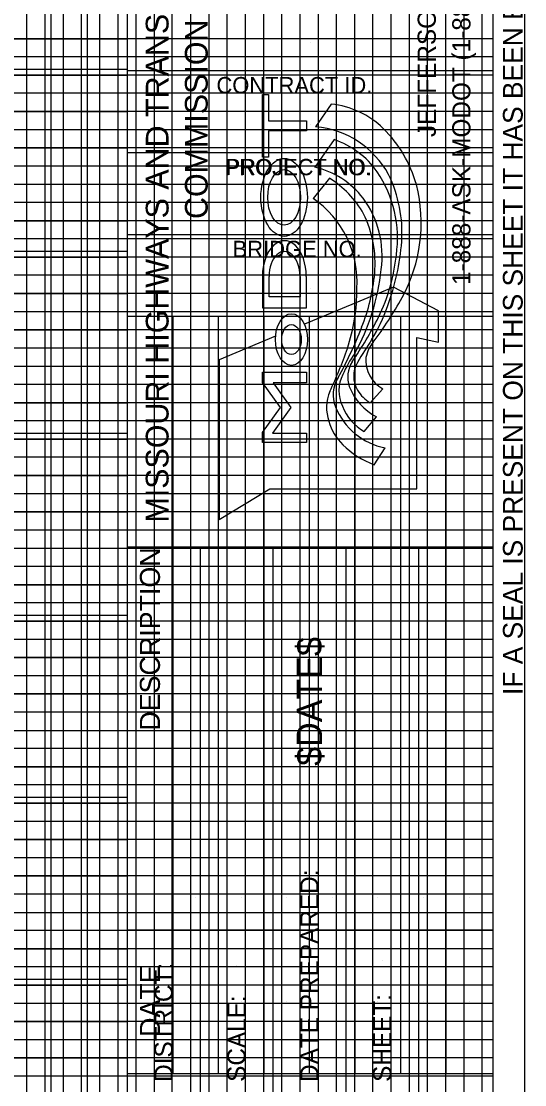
# Model space of a CAD drawing. Extents: x 0 to 31.6, y 0 to 20.8.
# Drawn here: x 28.84 to 31.6, y 10.27 to 16.11 of the extents above; entities that cross this region are included whole.
import ezdxf

# ---------------------------------------------------------------- set-up
doc = ezdxf.new("R2010")
doc.units = 0
for name, color, linetype in [('Border-Border', 7, 'Continuous'), ('Border-Bridge xsection major grid lines', 7, 'Continuous'), ('Border-Bridge xsection minor grid lines', 7, 'Continuous'), ('Border-Full profile major grid lines', 7, 'Continuous'), ('Border-Full xsection major grid lines', 7, 'Continuous'), ('Border-Full xsection minor grid lines', 7, 'Continuous'), ('Border-Plotting block', 7, 'Continuous'), ('Border-Title block - Final Plans Consultant Manual Seal', 7, 'Continuous'), ('Border-Title block - Final Plans Electronic Seal', 7, 'Continuous'), ('Border-Title block - Location Survey Electronic Seal', 7, 'Continuous'), ('Border-Xsection shape', 7, 'Continuous')]:
    doc.layers.add(name, color=color, linetype=linetype)

msp = doc.modelspace()

# ---------------------------------------------------------------- linework, layer by layer
at = {"layer": 'Border-Border'}
msp.add_line((31.425, 20.5875), (31.425, 0.2125), dxfattribs=at)
at = {"layer": 'Border-Bridge xsection major grid lines'}
for p, q in [((29.6649, 4.2046), (29.6649, 20.5875)), ((30.6649, 20.5875), (30.6649, 4.2046)), ((0.175, 15.2126), (31.4249, 15.2126)), ((0.175, 14.2126), (31.4249, 14.2126)), ((0.175, 13.2125), (31.4249, 13.2125)), ((0.175, 12.2125), (31.4249, 12.2125)), ((0.175, 11.2125), (31.4249, 11.2125))]:
    msp.add_line(p, q, dxfattribs=at)
at = {"layer": 'Border-Bridge xsection minor grid lines'}
for p, q in [((28.8649, 20.5875), (28.8649, 4.2046)), ((28.9649, 20.5875), (28.9649, 4.2046)), ((29.0649, 20.5875), (29.0649, 4.2046)), ((29.1649, 20.5875), (29.1649, 4.2046)), ((29.2649, 20.5875), (29.2649, 4.2046)), ((29.3649, 20.5875), (29.3649, 4.2046)), ((29.4649, 20.5875), (29.4649, 4.2046)), ((29.5649, 20.5875), (29.5649, 4.2046)), ((29.7649, 20.5875), (29.7649, 4.2046)), ((29.8649, 20.5875), (29.8649, 4.2046)), ((29.9649, 20.5875), (29.9649, 4.2046)), ((30.0649, 20.5875), (30.0649, 4.2046)), ((30.1649, 20.5875), (30.1649, 4.2046)), ((30.2649, 20.5875), (30.2649, 4.2046)), ((30.3649, 20.5875), (30.3649, 4.2046)), ((30.4649, 20.5875), (30.4649, 4.2046)), ((30.5649, 20.5875), (30.5649, 4.2046)), ((30.7649, 20.5875), (30.7649, 4.2046)), ((30.8649, 20.5875), (30.8649, 4.2046)), ((30.9649, 20.5875), (30.9649, 4.2046)), ((31.0649, 20.5875), (31.0649, 4.2046)), ((31.1649, 20.5875), (31.1649, 4.2046)), ((31.2649, 20.5875), (31.2649, 4.2046)), ((31.3649, 20.5875), (31.3649, 4.2046)), ((31.4249, 16.0126), (0.175, 16.0126)), ((31.4249, 15.9126), (0.175, 15.9126)), ((31.4249, 15.8126), (0.175, 15.8126)), ((31.4249, 15.7126), (0.175, 15.7126)), ((31.4249, 15.6126), (0.175, 15.6126)), ((31.4249, 15.5126), (0.175, 15.5126)), ((31.4249, 15.4126), (0.175, 15.4126)), ((31.4249, 15.3126), (0.175, 15.3126)), ((31.4249, 15.1126), (0.175, 15.1126)), ((31.4249, 15.0126), (0.175, 15.0126)), ((31.4249, 14.9126), (0.175, 14.9126)), ((31.4249, 14.8126), (0.175, 14.8126)), ((31.4249, 14.7126), (0.175, 14.7126)), ((31.4249, 14.6126), (0.175, 14.6126)), ((31.4249, 14.5126), (0.175, 14.5126)), ((31.4249, 14.4126), (0.175, 14.4126)), ((31.4249, 14.3126), (0.175, 14.3126)), ((31.4249, 14.1126), (0.175, 14.1126)), ((31.4249, 14.0125), (0.175, 14.0125)), ((31.4249, 13.9125), (0.175, 13.9125)), ((31.4249, 13.8125), (0.175, 13.8125)), ((31.4249, 13.7125), (0.175, 13.7125)), ((31.4249, 13.6125), (0.175, 13.6125)), ((31.4249, 13.5125), (0.175, 13.5125)), ((31.4249, 13.4125), (0.175, 13.4125)), ((31.4249, 13.3125), (0.175, 13.3125)), ((31.4249, 13.1125), (0.175, 13.1125)), ((31.4249, 13.0125), (0.175, 13.0125)), ((31.4249, 12.9125), (0.175, 12.9125)), ((31.4249, 12.8125), (0.175, 12.8125)), ((31.4249, 12.7125), (0.175, 12.7125)), ((31.4249, 12.6125), (0.175, 12.6125)), ((31.4249, 12.5125), (0.175, 12.5125)), ((31.4249, 12.4125), (0.175, 12.4125)), ((31.4249, 12.3125), (0.175, 12.3125)), ((31.4249, 12.1125), (0.175, 12.1125)), ((31.4249, 12.0125), (0.175, 12.0125)), ((31.4249, 11.9125), (0.175, 11.9125)), ((31.4249, 11.8125), (0.175, 11.8125)), ((31.4249, 11.7125), (0.175, 11.7125)), ((31.4249, 11.6125), (0.175, 11.6125)), ((31.4249, 11.5125), (0.175, 11.5125)), ((31.4249, 11.4125), (0.175, 11.4125)), ((31.4249, 11.3125), (0.175, 11.3125)), ((31.4249, 11.1125), (0.175, 11.1125)), ((31.4249, 11.0125), (0.175, 11.0125)), ((31.4249, 10.9125), (0.175, 10.9125)), ((31.4249, 10.8125), (0.175, 10.8125)), ((31.4249, 10.7125), (0.175, 10.7125)), ((31.4249, 10.6125), (0.175, 10.6125)), ((31.4249, 10.5125), (0.175, 10.5125)), ((31.4249, 10.4125), (0.175, 10.4125)), ((31.4249, 10.3125), (0.175, 10.3125))]:
    msp.add_line(p, q, dxfattribs=at)
at = {"layer": 'Border-Full profile major grid lines'}
for p, q in [((29.4171, 15.8436), (0.175, 15.8436)), ((29.4171, 14.8436), (0.175, 14.8436)), ((29.4171, 13.8436), (0.175, 13.8436)), ((29.4171, 12.8436), (0.175, 12.8436)), ((29.4171, 11.8436), (0.175, 11.8436)), ((29.4171, 10.8436), (0.175, 10.8436))]:
    msp.add_line(p, q, dxfattribs=at)
at = {"layer": 'Border-Full xsection major grid lines'}
for p, q in [((0.175, 15.2125), (29.4171, 15.2125)), ((0.175, 14.2125), (29.4171, 14.2125)), ((0.175, 13.2125), (29.4171, 13.2125)), ((0.175, 12.2125), (29.4171, 12.2125)), ((0.175, 11.2125), (29.4171, 11.2125))]:
    msp.add_line(p, q, dxfattribs=at)
at = {"layer": 'Border-Full xsection minor grid lines'}
for p, q in [((28.9999, 0.2125), (28.9999, 20.5875)), ((29.1999, 0.2125), (29.1999, 20.5875)), ((0.175, 16.0125), (29.4171, 16.0125)), ((0.175, 15.8125), (29.4171, 15.8125)), ((0.175, 15.6125), (29.4171, 15.6125)), ((0.175, 15.4125), (29.4171, 15.4125)), ((0.175, 15.0125), (29.4171, 15.0125)), ((0.175, 14.8125), (29.4171, 14.8125)), ((0.175, 14.6125), (29.4171, 14.6125)), ((0.175, 14.4125), (29.4171, 14.4125)), ((0.175, 14.0125), (29.4171, 14.0125)), ((0.175, 13.8125), (29.4171, 13.8125)), ((0.175, 13.6125), (29.4171, 13.6125)), ((0.175, 13.4125), (29.4171, 13.4125)), ((0.175, 13.0125), (29.4171, 13.0125)), ((0.175, 12.8125), (29.4171, 12.8125)), ((0.175, 12.6125), (29.4171, 12.6125)), ((0.175, 12.4125), (29.4171, 12.4125)), ((0.175, 12.0125), (29.4171, 12.0125)), ((0.175, 11.8125), (29.4171, 11.8125)), ((0.175, 11.6125), (29.4171, 11.6125)), ((0.175, 11.4125), (29.4171, 11.4125)), ((0.175, 11.0125), (29.4171, 11.0125)), ((0.175, 10.8125), (29.4171, 10.8125)), ((0.175, 10.6125), (29.4171, 10.6125)), ((0.175, 10.4125), (29.4171, 10.4125))]:
    msp.add_line(p, q, dxfattribs=at)
at = {"layer": 'Border-Plotting block'}
msp.add_lwpolyline([(0, 0), (31.5999, 0), (31.5999, 20.8), (0, 20.8)], close=True, dxfattribs=at)
at = {"layer": 'Border-Title block - Final Plans Consultant Manual Seal'}
for p, q in [((29.4171, 20.5875), (29.4171, 0.2125)), ((30.421, 15.9927), (30.421, 15.9927)), ((29.4171, 15.8376), (31.425, 15.8376)), ((30.421, 15.5427), (30.421, 15.5427)), ((29.4171, 15.3876), (31.425, 15.3876)), ((30.421, 15.0927), (30.421, 15.0927)), ((29.4171, 14.9376), (31.425, 14.9376)), ((30.421, 14.6427), (30.421, 14.6427)), ((29.4171, 14.4876), (31.425, 14.4876)), ((29.6671, 14.4876), (29.6671, 10.3272)), ((29.9171, 14.4876), (29.9171, 10.3272)), ((30.1671, 14.4876), (30.1671, 10.3272)), ((30.4171, 14.4876), (30.4171, 10.3272)), ((30.6671, 14.4876), (30.6671, 10.3272)), ((30.9171, 14.4876), (30.9171, 10.3272)), ((31.1671, 14.4876), (31.1671, 10.3272)), ((29.4171, 11.1172), (31.425, 11.1172)), ((29.4171, 10.3272), (31.425, 10.3272))]:
    msp.add_line(p, q, dxfattribs=at)
at = {"layer": 'Border-Title block - Final Plans Electronic Seal'}
for p, q in [((29.4171, 20.5875), (29.4171, 0.2125)), ((30.421, 15.9927), (30.421, 15.9927)), ((29.4171, 15.8376), (31.425, 15.8376)), ((30.421, 15.5427), (30.421, 15.5427)), ((29.4171, 15.3876), (31.425, 15.3876)), ((30.421, 15.0927), (30.421, 15.0927)), ((29.4171, 14.9376), (31.425, 14.9376)), ((30.421, 14.6427), (30.421, 14.6427)), ((29.4171, 14.4876), (31.425, 14.4876)), ((29.6671, 14.4876), (29.6671, 10.3272)), ((29.9171, 14.4876), (29.9171, 10.3272)), ((30.1671, 14.4876), (30.1671, 10.3272)), ((30.4171, 14.4876), (30.4171, 10.3272)), ((30.6671, 14.4876), (30.6671, 10.3272)), ((30.9171, 14.4876), (30.9171, 10.3272)), ((31.1671, 14.4876), (31.1671, 10.3272)), ((29.7921, 11.2965), (29.7921, 11.2965)), ((29.7921, 11.2965), (29.7921, 11.2965)), ((30.0421, 11.2965), (30.0421, 11.2965)), ((30.0421, 11.2965), (30.0421, 11.2965)), ((30.2921, 11.2965), (30.2921, 11.2965)), ((30.2921, 11.2965), (30.2921, 11.2965)), ((30.5421, 11.2965), (30.5421, 11.2965)), ((30.5421, 11.2965), (30.5421, 11.2965)), ((30.7921, 11.2965), (30.7921, 11.2965)), ((30.7921, 11.2965), (30.7921, 11.2965)), ((31.0421, 11.2965), (31.0421, 11.2965)), ((31.0421, 11.2965), (31.0421, 11.2965)), ((31.296, 11.2965), (31.296, 11.2965)), ((31.296, 11.2965), (31.296, 11.2965)), ((29.4171, 11.1172), (31.425, 11.1172)), ((29.7921, 10.7222), (29.7921, 10.7222)), ((29.7921, 10.7222), (29.7921, 10.7222)), ((30.0421, 10.7222), (30.0421, 10.7222)), ((30.0421, 10.7222), (30.0421, 10.7222)), ((30.2921, 10.7222), (30.2921, 10.7222)), ((30.2921, 10.7222), (30.2921, 10.7222)), ((30.5421, 10.7222), (30.5421, 10.7222)), ((30.5421, 10.7222), (30.5421, 10.7222)), ((30.7921, 10.7222), (30.7921, 10.7222)), ((30.7921, 10.7222), (30.7921, 10.7222)), ((31.0421, 10.7222), (31.0421, 10.7222)), ((31.0421, 10.7222), (31.0421, 10.7222)), ((31.296, 10.7222), (31.296, 10.7222)), ((31.296, 10.7222), (31.296, 10.7222)), ((29.4171, 10.3272), (31.425, 10.3272))]:
    msp.add_line(p, q, dxfattribs=at)
at = {"layer": 'Border-Title block - Location Survey Electronic Seal'}
for p, q in [((29.4171, 20.5875), (29.4171, 0.2125)), ((30.5365, 15.6526), (30.4519, 15.5284)), ((30.5541, 15.4582), (30.4483, 15.3072)), ((30.5272, 15.2463), (30.4378, 15.1351)), ((30.16, 14.7067), (30.16, 14.5344)), ((30.1963, 14.5938), (30.1963, 14.7067)), ((30.3662, 14.7067), (30.3662, 14.5938)), ((30.4008, 14.5344), (30.4008, 14.7067)), ((30.8803, 14.6472), (30.3903, 14.4434)), ((31.1267, 14.5169), (30.8803, 14.6472)), ((30.3662, 14.5938), (30.1963, 14.5938)), ((30.16, 14.5344), (30.4008, 14.5344)), ((31.1267, 14.3458), (31.1267, 14.5169)), ((30.2315, 14.3774), (29.922, 14.2486)), ((31.0071, 13.5396), (31.0071, 14.3712)), ((31.0071, 14.3712), (31.1267, 14.3458)), ((29.922, 14.2486), (29.922, 13.3702)), ((30.7517, 14.0128), (30.821, 14.0888)), ((30.7188, 13.8546), (30.7857, 13.9352)), ((30.7729, 13.6717), (30.8329, 13.7643)), ((29.922, 13.3702), (30.2004, 13.5396)), ((30.2004, 13.5396), (31.0071, 13.5396)), ((29.4171, 13.2202), (31.425, 13.2202)), ((29.8171, 13.2202), (29.8171, 7.2202)), ((30.2171, 13.2202), (30.2171, 7.2202)), ((30.6171, 13.2202), (30.6171, 7.2202)), ((31.0171, 13.2202), (31.0171, 7.2202)), ((29.6171, 11.4138), (29.6171, 11.4138)), ((30.8171, 10.9502), (30.8171, 10.9502)), ((30.0171, 10.9212), (30.0171, 10.9212))]:
    msp.add_line(p, q, dxfattribs=at)
for points in [[(30.1599, 15.3619), (30.1599, 15.7063), (30.1934, 15.7063), (30.1934, 15.5608), (30.4008, 15.5608), (30.4008, 15.5063), (30.1934, 15.5063), (30.1934, 15.3619)], [(30.4008, 13.794), (30.1592, 13.794), (30.1592, 13.8486), (30.2588, 13.9854), (30.16, 14.1242), (30.16, 14.1797), (30.4008, 14.1797), (30.4008, 14.1223), (30.2185, 14.1223), (30.3164, 13.9854), (30.2147, 13.8448), (30.4008, 13.8448)]]:
    msp.add_lwpolyline(points, close=True, dxfattribs=at)
for centre, radius, start, end in [((30.4952, 15.1888), 0.4656, 45.16931, 84.90202), ((30.4076, 15.0235), 0.5069, 28.57249, 84.98895), ((30.3292, 15.0191), 0.7029, 15.82215, 45.3322), ((30.3947, 14.9991), 0.486, 35.48059, 70.84743), ((30.3361, 14.8436), 0.477, 37.82053, 76.39644), ((30.2462, 14.9161), 0.6553, 351.92721, 33.85401), ((30.1918, 14.9463), 0.7342, 356.25263, 25.80365), ((30.2447, 14.7868), 0.5393, 29.26655, 58.41911), ((30.1706, 15.0012), 0.8608, 331.45894, 14.08516), ((30.1256, 14.677), 0.5543, 55.72742, 55.72758), ((30.1256, 14.677), 0.5543, 356.10332, 55.7272), ((30.2854, 14.8202), 0.5315, 351.87184, 36.46402), ((30.1519, 14.7759), 0.6267, 355.20478, 25.98369), ((29.6592, 14.9902), 1.2685, 339.27778, 355.84654), ((29.8531, 14.9368), 1.048, 334.30971, 353.82369), ((29.6238, 14.8634), 1.1937, 330.80189, 354.30584), ((29.6939, 14.8284), 1.0875, 338.33661, 354.46616), ((29.6632, 14.6333), 1.0155, 341.46898, 0.34157), ((29.0087, 15.6586), 2.1957, 323.25469, 330.87553), ((30.017, 14.8198), 0.8742, 328.33342, 341.42803), ((28.929, 15.4287), 2.0944, 325.33774, 333.14131), ((28.6965, 15.2), 2.1518, 330.82713, 338.94553), ((33.478, 12.5564), 3.2616, 146.40943, 149.03928), ((30.9123, 14.2249), 0.1877, 140.18798, 168.85058), ((28.5928, 15.004), 2.1483, 334.37273, 341.16645), ((31.1325, 13.9405), 0.5778, 143.87617, 156.87144), ((30.9045, 14.245), 0.177, 174.75269, 241.86614), ((30.7955, 14.1526), 0.167, 149.40426, 197.76384), ((30.8136, 14.1585), 0.1526, 150.25518, 210.64132), ((30.7203, 14.057), 0.1729, 147.01991, 203.02392), ((30.7795, 14.0777), 0.1996, 153.27349, 205.14999), ((30.9419, 14.2254), 0.3295, 202.06293, 241.72012), ((30.7493, 13.9848), 0.2373, 157.70916, 198.17281), ((30.8522, 14.1848), 0.1993, 211.49535, 239.68972), ((30.9032, 14.1256), 0.3681, 201.72885, 258.99607), ((30.8578, 14.0965), 0.279, 201.81038, 240.11136), ((30.7878, 13.9817), 0.2733, 195.0361, 226.99124), ((30.9511, 14.1377), 0.4989, 225.49883, 249.07866)]:
    msp.add_arc(centre, radius, start, end, dxfattribs=at)
for centre, major_axis, ratio in [((30.2788, 15.1408), (0, 0.2144), 0.595517), ((30.2788, 15.1408), (0, -0.153), 0.589579), ((30.3191, 14.3595), (0, 0.1416), 0.623747), ((30.3191, 14.3595), (0, 0.0823), 0.65252)]:
    msp.add_ellipse(centre, major_axis=major_axis, ratio=ratio, dxfattribs=at)
for centre, major_axis, ratio in [((30.2803, 14.7067), (0, -0.1961), 0.614143), ((30.2812, 14.7067), (0, -0.1368), 0.62091)]:
    msp.add_ellipse(centre, major_axis=major_axis, ratio=ratio, start_param=1.570796, end_param=4.712389, dxfattribs=at)
at = {"layer": 'Border-Xsection shape'}
msp.add_lwpolyline([(29.4171, 0.2125), (0.175, 0.2125), (0.175, 20.5875), (29.4171, 20.5875)], close=True, dxfattribs=at)

# ---------------------------------------------------------------- texts
at = {"layer": 'Border-Border'}
msp.add_text('IF A SEAL IS PRESENT ON THIS SHEET IT HAS BEEN ELECTRONICALLY SEALED AND DATED.  ', height=0.108267, rotation=90, dxfattribs=at).set_placement((31.5888, 12.4068))
at = {"layer": 'Border-Title block - Final Plans Consultant Manual Seal'}
for s, height, p in [('CONTRACT ID.', 0.09, (29.9074, 15.7122)), ('PROJECT NO.', 0.09, (29.9518, 15.2622)), ('PROJECT NO.', 0.088582, (29.9592, 15.2629)), ('BRIDGE NO.', 0.09, (29.9962, 14.8122))]:
    msp.add_text(s, height=height, dxfattribs=at).set_placement(p)
for s, height, p in [('DESCRIPTION', 0.110236, (29.597, 12.2106)), ('DATE', 0.11024, (29.597, 10.5282))]:
    msp.add_text(s, height=height, rotation=90, dxfattribs=at).set_placement(p)
at = {"layer": 'Border-Title block - Final Plans Electronic Seal'}
for s, height, p in [('CONTRACT ID.', 0.09, (29.9074, 15.7122)), ('PROJECT NO.', 0.088582, (29.9592, 15.2629)), ('PROJECT NO.', 0.088582, (29.9592, 15.2629)), ('BRIDGE NO.', 0.09, (29.9962, 14.8122))]:
    msp.add_text(s, height=height, dxfattribs=at).set_placement(p)
for s, height, p in [('DESCRIPTION', 0.110236, (29.597, 12.2106)), ('DATE', 0.11024, (29.597, 10.5282))]:
    msp.add_text(s, height=height, rotation=90, dxfattribs=at).set_placement(p)
at = {"layer": 'Border-Title block - Location Survey Electronic Seal'}
for s, height, p in [('JEFFERSON CITY, MO 65102', 0.1, (31.112, 15.4723)), ('MISSOURI HIGHWAYS AND TRANSPORTATION', 0.125, (29.6442, 13.3537)), ('1-888-ASK-MODOT (1-888-275-6636)', 0.1, (31.302, 14.6595)), ('COMMISSION', 0.125, (29.8592, 15.022)), ('$DATE$', 0.14, (30.4871, 12.0174)), ('DATE PREPARED:', 0.1, (30.4671, 10.281)), ('DISTRICT:', 0.1, (29.6671, 10.281)), ('SHEET:', 0.1, (30.8671, 10.281)), ('SCALE:', 0.1, (30.0671, 10.281))]:
    msp.add_text(s, height=height, rotation=90, dxfattribs=at).set_placement(p)

doc.saveas('drawing.dxf')
